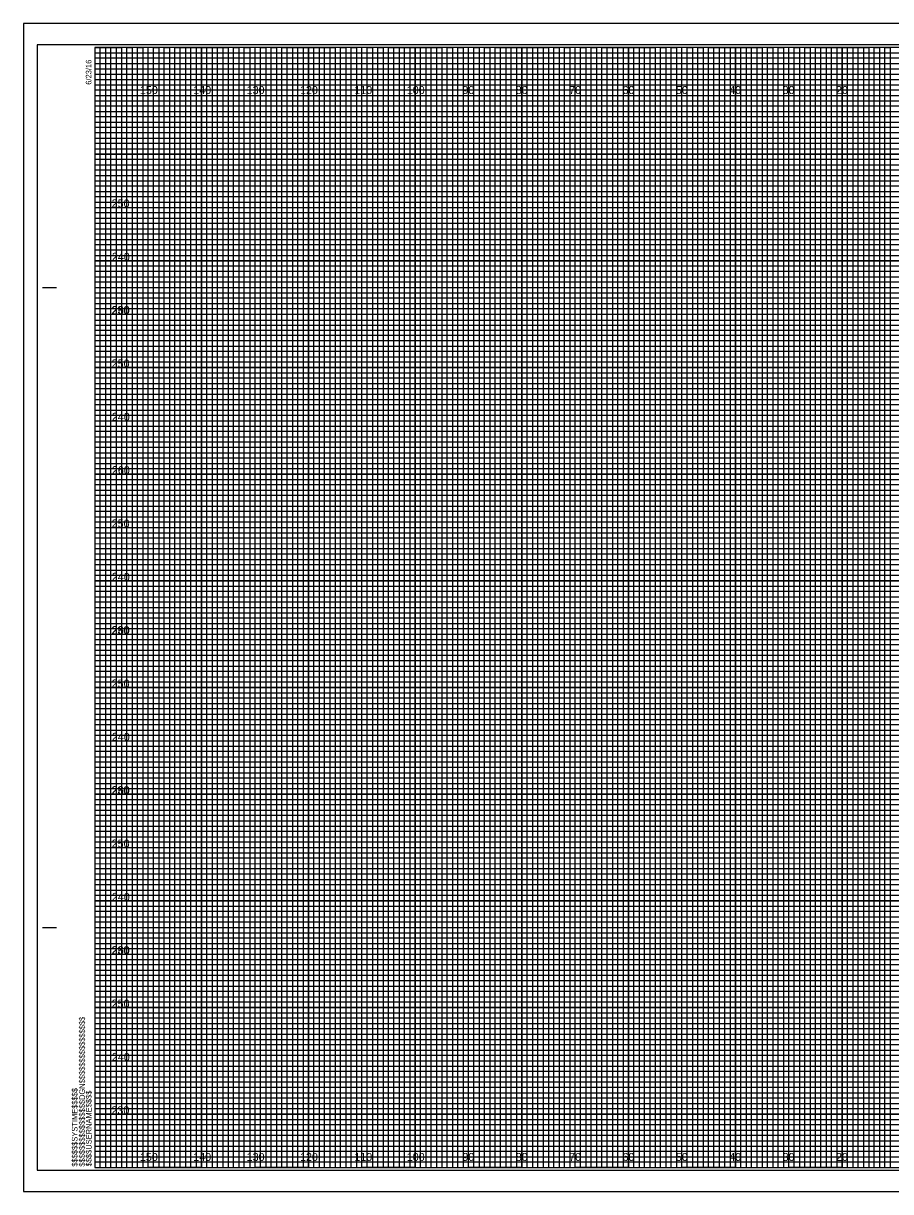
# Model space of a CAD drawing. Extents: x -13 to 359, y -5 to 2854.
# Drawn here: x -13.4 to 149.1, y 435.5 to 654.5 of the extents above; entities that cross this region are included whole.
import ezdxf

# ---------------------------------------------------------------- set-up
doc = ezdxf.new("R2010")
doc.units = 0
for name, color, linetype in [('Exist Cross Section Cell', 7, 'Continuous'), ('Exist XS Ground Line', 7, 'Continuous'), ('Prop CMT Concrete Structures', 7, 'Continuous'), ('Prop CMT DNC', 7, 'Continuous'), ('Prop CMT Pvmt Course 1', 7, 'Continuous'), ('Prop CMT Pvmt Course 1 CG', 7, 'Continuous'), ('Prop CMT Pvmt Course 2', 7, 'Continuous'), ('Prop CMT Shear Line', 7, 'Continuous'), ('Prop CMT Slope Grass', 7, 'Continuous'), ('Prop CMT Subgrade Earthwork', 7, 'Continuous'), ('Scratch_Level_0', 7, 'Continuous')]:
    doc.layers.add(name, color=color, linetype=linetype)

msp = doc.modelspace()

# ---------------------------------------------------------------- linework, layer by layer
at = {"layer": 'Exist XS Ground Line'}
for p, q in [((10, 650), (0, 650)), ((10, 440), (10, 650)), ((30, 650), (20, 650)), ((20, 650), (20, 440)), ((30, 440), (30, 650)), ((50, 650), (40, 650)), ((40, 650), (40, 440)), ((50, 440), (50, 650)), ((70, 650), (60, 650)), ((60, 650), (60, 440)), ((70, 440), (70, 650)), ((90, 650), (80, 650)), ((80, 650), (80, 440)), ((90, 440), (90, 650)), ((110, 650), (100, 650)), ((100, 650), (100, 440)), ((110, 440), (110, 650)), ((130, 650), (120, 650)), ((120, 650), (120, 440)), ((130, 440), (130, 650)), ((150, 650), (140, 650)), ((140, 650), (140, 440)), ((20, 440), (10, 440)), ((40, 440), (30, 440)), ((60, 440), (50, 440)), ((80, 440), (70, 440)), ((100, 440), (90, 440)), ((120, 440), (110, 440)), ((140, 440), (130, 440))]:
    msp.add_line(p, q, dxfattribs=at)
for points in [[(0, 640), (320, 640), (320, 630), (0, 630)], [(0, 620), (320, 620), (320, 610), (0, 610)], [(0, 600), (320, 600), (320, 590), (0, 590)], [(0, 580), (320, 580), (320, 570), (0, 570)], [(0, 560), (320, 560), (320, 550), (0, 550)], [(0, 540), (320, 540), (320, 530), (0, 530)], [(0, 520), (320, 520), (320, 510), (0, 510)], [(0, 500), (320, 500), (320, 490), (0, 490)], [(0, 480), (320, 480), (320, 470), (0, 470)], [(0, 460), (320, 460), (320, 450), (0, 450)]]:
    msp.add_lwpolyline(points, dxfattribs=at)
at = {"layer": 'Prop CMT Concrete Structures'}
for p, q in [((-9.8, 605), (-7.3, 605)), ((-9.7, 605), (-7.2, 605)), ((-9.8, 485), (-7.3, 485)), ((-9.7, 485), (-7.2, 485)), ((0, 440), (0, 440)), ((0, 440), (0, 440)), ((0, 440), (0, 440)), ((0, 440), (0, 440)), ((0, 440), (0, 440)), ((0, 440), (0, 440)), ((0, 440), (0, 440))]:
    msp.add_line(p, q, dxfattribs=at)
msp.add_lwpolyline([(320, 650), (0, 650), (0, 440), (320, 440)], close=True, dxfattribs=at)
at = {"layer": 'Prop CMT DNC'}
for p, q in [((323.3, 654.5), (-13.4, 654.5)), ((-13.4, 654.5), (-13.4, 435.5)), ((-13.4, 435.5), (323.3, 435.5))]:
    msp.add_line(p, q, dxfattribs=at)
at = {"layer": 'Prop CMT Pvmt Course 1'}
for p, q in [((0, 649), (260, 649)), ((260, 647.98), (0, 647.98)), ((0, 647.98), (0, 647)), ((0, 647), (260, 647)), ((260, 645.89), (0, 645.89)), ((0, 645.89), (0, 644)), ((0, 644), (320, 644))]:
    msp.add_line(p, q, dxfattribs=at)
for points in [[(0, 643), (270, 643), (320, 643), (320, 642), (0, 642)], [(0, 641), (320, 641), (320, 639), (0, 639)], [(0, 638), (320, 638), (320, 637), (0, 636.98)], [(0, 636), (320, 636), (320, 634), (0, 634)], [(0, 633), (320, 633), (320, 632), (0, 632)], [(0, 631), (320, 631), (320, 629), (0, 629)], [(0, 628), (320, 628), (320, 627), (0, 627)], [(0, 626), (320, 626), (320, 624), (0, 624)], [(0, 623), (320, 623), (320, 622), (0, 622)], [(0, 621), (320, 621), (320, 619), (0, 619)], [(0, 618), (320, 618), (320, 617), (0, 617)], [(0, 616), (320, 616), (320, 613.95), (320, 613), (320, 612), (0, 612)], [(0, 614), (320, 614), (320, 613), (0, 613)], [(0, 611), (320, 611), (320, 609), (0, 609.03)], [(0, 609.03), (320, 609), (320, 608), (0, 608)], [(0, 607), (320, 607), (320, 606), (0, 606)], [(0, 604), (320, 604), (320, 603), (0, 603)], [(0, 602), (320, 602), (320, 601), (0, 601)], [(-0.07, 598.89), (320, 598.89), (320, 597.88), (-0.07, 597.88)], [(0, 597), (320, 597), (320, 596), (0, 596)], [(0, 594), (320, 594), (320, 593), (0, 593)], [(0, 592), (320, 592), (320, 591), (0, 591)], [(0, 589), (320, 589), (320, 588), (0, 588)], [(0, 587), (320, 587), (320, 586), (0, 586)], [(0, 584), (320, 584), (320, 583), (0, 583)], [(0, 582), (320, 582), (320, 581), (0, 581)], [(0, 579), (320, 579), (319.99, 577.98), (0, 578)], [(0, 577), (320, 577), (320, 576), (0, 576)], [(0, 574), (320, 574), (320, 573), (0, 573)], [(0, 572), (320, 572), (320, 571), (0, 571)], [(0, 569), (320, 569), (320, 568), (0, 568)], [(0, 567), (320, 567), (320, 566), (0, 566)], [(0, 564), (320, 564), (320, 563), (0, 563)], [(0, 562), (320, 562), (320, 561), (0, 561)], [(0, 559), (320, 559), (320, 558), (0, 558)], [(0, 556.99), (320.07, 556.91), (320, 556), (0, 556)], [(0, 554), (320, 554), (320, 553), (0, 553)], [(0, 552), (320, 552), (320, 551), (0, 551)], [(0, 549), (320, 549), (320, 548), (0, 548)], [(0, 547), (320, 547), (320, 546), (0, 546)], [(0, 544), (320, 544), (320, 543), (0, 543)], [(0, 542), (320, 542), (320, 541), (0, 541)], [(0, 539), (320, 539), (320, 538), (0, 538)], [(0, 537), (320, 537), (320, 536), (0, 536)], [(0, 534), (320, 534), (320, 533), (0, 533)], [(0, 532), (320, 532), (320, 531), (0, 531)], [(0, 529), (320, 529), (320, 528), (0, 528)], [(0, 527), (320, 527), (320, 526), (0, 526)], [(0, 524), (320, 524), (320, 523), (0, 523)], [(0, 522), (320, 522), (320, 521), (0, 521)], [(0, 519), (320, 519), (319.99, 517.98), (0, 518)], [(0, 517), (320, 517), (320, 516), (0, 516)], [(0, 514), (320, 514), (320, 513), (0, 513)], [(0, 512), (320, 512), (320, 511), (0, 511)], [(0, 509), (320, 509), (320, 508), (0, 508)], [(0, 507), (320, 507), (320, 506), (0, 506)], [(0, 504), (320, 504), (320, 503), (0, 503)], [(0, 502), (320, 502), (320, 501), (0, 501)], [(0, 499), (320, 499), (320, 498), (0, 498)], [(0, 496.99), (320.07, 496.91), (320, 496), (0, 496)], [(0, 494), (320, 494), (320, 493), (0, 493)], [(0, 492), (320, 492), (320, 491), (0, 491)], [(0, 489), (320, 489), (320, 488), (0, 488)], [(0, 487), (320, 487), (320, 486), (0, 486)], [(0, 484), (320, 484), (320, 483), (0, 483)], [(0, 482), (320, 482), (320, 481), (0, 481)], [(0, 479), (320, 479), (320, 478), (0, 478)], [(0, 477), (320, 477), (320, 476), (0, 476)], [(0, 474), (320, 474), (320, 473), (0, 473)], [(0, 472), (320, 472), (320, 471), (0, 471)], [(0, 469), (320, 469), (320, 468), (0, 468)], [(0, 467), (320, 467), (320, 466), (0, 466)], [(0, 464), (320, 464), (320, 463), (0, 463)], [(0, 462), (320, 462), (320, 461), (0, 461)], [(0, 459), (320, 459), (320, 458), (0, 458)], [(0, 457), (320, 457), (320, 456), (0, 456)], [(0, 454), (320, 454), (320, 453), (0, 453)], [(0, 452), (320, 452), (320, 451), (0, 451)], [(0, 449), (320, 449), (320, 448), (0, 448)], [(0, 447), (320, 447), (320, 446), (0, 446)], [(0, 444), (320, 444), (320, 443), (0, 443)], [(0, 442), (320, 442), (320, 441), (0, 441)]]:
    msp.add_lwpolyline(points, dxfattribs=at)
at = {"layer": 'Prop CMT Pvmt Course 1 CG'}
for points in [[(0, 440), (1, 440), (1, 650), (2, 650), (2, 440)], [(2, 440), (3, 440), (3, 650), (4, 650), (4, 440)], [(5, 440), (6, 440), (6, 650), (7, 650), (7, 440)], [(7, 440), (8, 440), (8, 650), (9, 650), (9, 440)], [(10, 440), (11, 440), (11, 650), (12, 650), (12, 440)], [(12, 440), (13, 440), (13, 650), (14, 650), (14, 440)], [(15, 440), (16, 440), (16, 650), (17, 650), (17, 440)], [(17, 440), (18, 440), (18, 650), (19, 650), (19, 440)], [(20, 440), (21, 440), (21, 650), (22, 650), (22, 440)], [(22, 440), (23, 440), (23, 650), (24, 650), (24, 440)], [(25, 440), (26, 440), (26, 650), (27, 650), (27, 440)], [(27, 440), (28, 440), (28, 650), (29, 650), (29, 440)], [(30, 440), (31, 440), (31, 650), (32, 650), (32, 440)], [(32, 440), (33, 440), (33, 650), (34, 650), (34, 440)], [(35, 440), (36, 440), (36, 650), (37, 650), (37, 440)], [(37, 440), (38, 440), (38, 650), (39, 650), (39, 440)], [(40, 440), (41, 440), (41, 650), (42, 650), (42, 440)], [(42, 440), (43, 440), (43, 650), (44, 650), (44, 440)], [(45, 440), (46, 440), (46, 650), (47, 650), (47, 440)], [(47, 440), (48, 440), (48, 650), (49, 650), (49, 440)], [(50, 440), (51, 440), (51, 650), (52, 650), (52, 440)], [(52, 440), (53, 440), (53, 650), (54, 650), (54, 440)], [(55, 440), (56, 440), (56, 650), (57, 650), (57, 440)], [(57, 440), (58, 440), (58, 650), (59, 650), (59, 440)], [(60, 440), (61, 440), (61, 650), (62, 650), (62, 440)], [(62, 440), (63, 440), (63, 650), (64, 650), (64, 440)], [(65, 440), (66, 440), (66, 650), (67, 650), (67, 440)], [(67, 440), (68, 440), (68, 650), (69, 650), (69, 440)], [(70, 440), (71, 440), (71, 650), (72, 650), (72, 440)], [(72, 440), (73, 440), (73, 650), (74, 650), (74, 440)], [(75, 440), (76, 440), (76, 650), (77, 650), (77, 440)], [(77, 440), (78, 440), (78, 650), (79, 650), (79, 440)], [(80, 440), (81, 440), (81, 650), (82, 650), (82, 440)], [(82, 440), (83, 440), (83, 650), (84, 650), (84, 440)], [(85, 440), (86, 440), (86, 650), (87, 650), (87, 440)], [(87, 440), (88, 440), (88, 650), (89, 650), (89, 440)], [(90, 440), (91, 440), (91, 650), (92, 650), (92, 440)], [(92, 440), (93, 440), (93, 650), (94, 650), (94, 440)], [(95, 440), (96, 440), (96, 650), (97, 650), (97, 440)], [(97, 440), (98, 440), (98, 650), (99, 650), (99, 440)], [(100, 440), (101, 440), (101, 650), (102, 650), (102, 440)], [(102, 440), (103, 440), (103, 650), (104, 650), (104, 440)], [(105, 440), (106, 440), (106, 650), (107, 650), (107, 440)], [(107, 440), (108, 440), (108, 650), (109, 650), (109, 440)], [(110, 440), (111, 440), (111, 650), (112, 650), (112, 440)], [(112, 440), (113, 440), (113, 650), (114, 650), (114, 440)], [(115, 440), (116, 440), (116, 650), (117, 650), (117, 440)], [(117, 440), (118, 440), (118, 650), (119, 650), (119, 440)], [(120, 440), (121, 440), (121, 650), (122, 650), (122, 440)], [(122, 440), (123, 440), (123, 650), (124, 650), (124, 440)], [(125, 440), (126, 440), (126, 650), (127, 650), (127, 440)], [(127, 440), (128, 440), (128, 650), (129, 650), (129, 440)], [(130, 440), (131, 440), (131, 650), (132, 650), (132, 440)], [(132, 440), (133, 440), (133, 650), (134, 650), (134, 440)], [(135, 440), (136, 440), (136, 650), (137, 650), (137, 440)], [(137, 440), (138, 440), (138, 650), (139, 650), (139, 440)], [(140, 440), (141, 440), (141, 650), (142, 650), (142, 440)], [(142, 440), (143, 440), (143, 650), (144, 650), (144, 440)], [(145, 440), (146, 440), (146, 650), (147, 650), (147, 440)], [(147, 440), (148, 440), (148, 650), (149, 650), (149, 440)]]:
    msp.add_lwpolyline(points, dxfattribs=at)
at = {"layer": 'Prop CMT Shear Line'}
for p, q in [((10, 440), (10, 650)), ((20, 440), (20, 650)), ((30, 440), (30, 650)), ((40, 440), (40, 650)), ((50, 440), (50, 650)), ((60, 440), (60, 650)), ((70, 440), (70, 650)), ((80, 440), (80, 650)), ((90, 440), (90, 650)), ((100, 440), (100, 650)), ((110, 440), (110, 650)), ((120, 440), (120, 650)), ((130, 440), (130, 650)), ((140, 440), (140, 650)), ((0, 640), (320, 640)), ((0, 630), (320, 630)), ((0, 620), (320, 620)), ((0, 610), (320, 610)), ((0, 600), (320, 600)), ((0, 590), (320, 590)), ((0, 580), (320, 580)), ((0, 570), (320, 570)), ((0, 560), (320, 560)), ((0, 550), (320, 550)), ((0, 540), (320, 540)), ((0, 530), (320, 530)), ((0, 520), (320, 520)), ((0, 510), (320, 510)), ((0, 500), (320, 500)), ((0, 490), (320, 490)), ((0, 480), (320, 480)), ((0, 470), (320, 470)), ((0, 460), (320, 460)), ((0, 450), (320, 450))]:
    msp.add_line(p, q, dxfattribs=at)
at = {"layer": 'Prop CMT Slope Grass'}
msp.add_lwpolyline([(-10.8, 439.5), (322.4, 439.5), (322.4, 650.5), (-10.8, 650.5)], close=True, dxfattribs=at)
at = {"layer": 'Prop CMT Subgrade Earthwork'}
msp.add_lwpolyline([(-13.4, 435.5), (323.3, 435.5), (323.3, 654.5), (-13.4, 654.5)], close=True, dxfattribs=at)
at = {"layer": 'Scratch_Level_0'}
for points in [[(0, 650), (5, 650), (5, 440), (15, 440), (15, 650), (25, 650), (25, 440), (35, 440), (35, 650), (45, 650), (45, 440), (55, 440), (55, 650), (65, 650), (65, 440), (75, 440), (75, 650), (85, 650), (85, 440), (95, 440), (95, 650), (105, 650), (105, 440), (115, 440), (115, 650), (125, 650), (125, 440), (135, 440), (135, 650), (145, 650), (145, 440), (155, 440)], [(0, 645), (275, 645)], [(0, 625), (320, 625), (320, 635), (0, 635)], [(0, 605), (320, 605), (320, 615), (0, 615)], [(0, 585), (320, 585), (320, 595), (0, 595)], [(0, 565), (320, 565), (320, 575), (0, 575)], [(0, 545), (320, 545), (320, 555), (0, 555)], [(0, 525), (320, 525), (320, 535), (0, 535)], [(0, 505), (320, 505), (320, 515), (0, 515)], [(0, 485), (320, 485), (320, 495), (0, 495)], [(0, 465), (320, 465), (320, 475), (0, 475)], [(0, 445), (320, 445), (320, 455), (0, 455)]]:
    msp.add_lwpolyline(points, dxfattribs=at)

# ---------------------------------------------------------------- texts
at = {"layer": 'Exist Cross Section Cell'}
for s, p in [('150', (8.44, 641.25)), ('140', (18.44, 641.25)), ('130', (28.44, 641.25)), ('120', (38.44, 641.25)), ('110', (48.62, 641.25)), ('100', (58.44, 641.25)), ('90', (68.86, 641.25)), ('80', (78.86, 641.25)), ('70', (88.86, 641.25)), ('60', (98.86, 641.25)), ('50', (108.86, 641.25)), ('40', (118.86, 641.25)), ('30', (128.86, 641.25)), ('20', (138.86, 641.25)), ('150', (8.44, 441.25)), ('140', (18.44, 441.25)), ('130', (28.44, 441.25)), ('120', (38.44, 441.25)), ('110', (48.62, 441.25)), ('100', (58.44, 441.25)), ('90', (68.86, 441.25)), ('80', (78.86, 441.25)), ('70', (88.86, 441.25)), ('60', (98.86, 441.25)), ('50', (108.86, 441.25)), ('40', (118.86, 441.25)), ('30', (128.86, 441.25)), ('20', (138.86, 441.25))]:
    msp.add_text(s, height=1.5, dxfattribs=at).set_placement(p)
at = {"layer": 'Prop CMT Concrete Structures'}
for s, p in [('6/23/16', (-0.65, 643)), ('$$$$$$$$$$$$$$$$DGN$$$$$$$$$$$$$$$$', (-1.88, 440.18)), ('$$$$$$SYSTIME$$$$$', (-3.26, 440.18)), ('$$$$USERNAME$$$$', (-0.62, 440.23))]:
    msp.add_text(s, height=1.05, rotation=90, dxfattribs=at).set_placement(p)
at = {"layer": 'Prop CMT Pvmt Course 2'}
for s, p in [('250', (3.15, 620)), ('240', (3.19, 610)), ('230', (3.11, 600)), ('260', (3.19, 600)), ('250', (3.15, 590)), ('240', (3.19, 580)), ('260', (3.19, 570)), ('250', (3.15, 560)), ('240', (3.19, 550)), ('230', (3.11, 540)), ('260', (3.19, 540)), ('250', (3.15, 530)), ('240', (3.19, 520)), ('230', (3.11, 510)), ('260', (3.19, 510)), ('250', (3.15, 500)), ('240', (3.19, 490)), ('230', (3.11, 480)), ('260', (3.19, 480)), ('250', (3.15, 470)), ('240', (3.19, 460)), ('230', (3.11, 450))]:
    msp.add_text(s, height=1.5, dxfattribs=at).set_placement(p)

doc.saveas('drawing.dxf')
